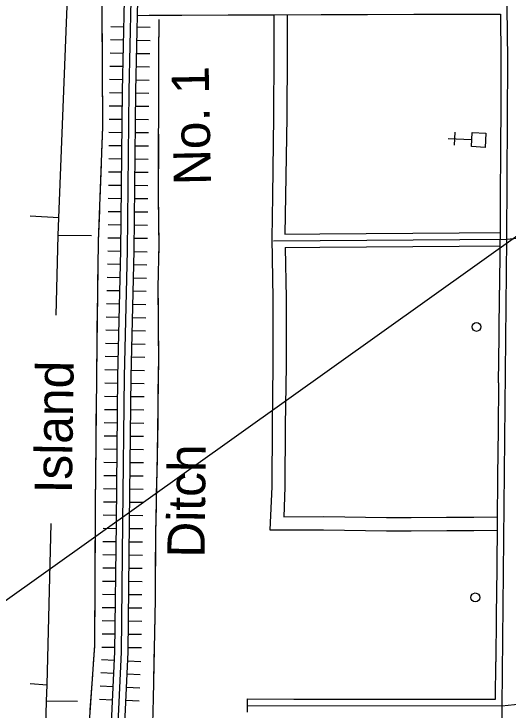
# Model space of a CAD drawing. Extents: x -4306 to 3843, y 131 to 8341.
# Drawn here: x -2826 to -1926, y 1950 to 3215 of the extents above; entities that cross this region are included whole.
import ezdxf

# ---------------------------------------------------------------- set-up
doc = ezdxf.new("R2010")
doc.units = 0
for name, color, linetype in [('31', 7, 'Continuous'), ('32', 7, 'Continuous'), ('4', 7, 'Continuous'), ('45', 7, 'Continuous'), ('46', 7, 'Continuous'), ('50', 7, 'Continuous'), ('52', 7, 'Continuous'), ('56', 7, 'Continuous'), ('57', 7, 'Continuous'), ('58', 7, 'Continuous'), ('63', 7, 'Continuous')]:
    doc.layers.add(name, color=color, linetype=linetype)

msp = doc.modelspace()

# ---------------------------------------------------------------- linework, layer by layer
at = {"layer": '31'}
for p, q in [((-1940.2, 3215.1), (-1939.2, 3135.4)), ((-1939.2, 3133.3), (-1939.6, 3051.1)), ((-1939.2, 3135.4), (-1939.2, 3133.3)), ((-1940.5, 2882.2), (-1940.9, 2817.8)), ((-1940.9, 2817.8), (-1941.1, 2793.8)), ((-1941.1, 2793.8), (-1941.9, 2713.3)), ((-1943.6, 2544.3), (-1944.4, 2459.8)), ((-1944.4, 2459.8), (-1945.3, 2375.3)), ((-1947, 2206.3), (-1947.9, 2121.9)), ((-1947.9, 2121.9), (-1948.7, 2037.4))]:
    msp.add_line(p, q, dxfattribs=at)
for points in [[(-1939.6, 3051.1), (-1940.1, 2966.7)], [(-1940.1, 2966.7), (-1940.5, 2882.2)], [(-1942.7, 2628.8), (-1941.9, 2713.3)], [(-1943.6, 2544.3), (-1942.7, 2628.8)], [(-1945.3, 2375.3), (-1946.2, 2290.8)], [(-1946.2, 2290.8), (-1947, 2206.3)], [(-1949.4, 1969.3), (-1948.7, 2037.4)]]:
    msp.add_lwpolyline(points, dxfattribs=at)
at = {"layer": '32'}
for p, q in [((-2097.6, 3214.6), (-2013.1, 3214.8)), ((-2013.1, 3214.8), (-1940.2, 3215.1)), ((-2601, 3212.3), (-2579.6, 3213)), ((-2579.6, 3213), (-2520.1, 3213.2)), ((-2520.1, 3213.2), (-2435.6, 3213.5)), ((-2435.6, 3213.5), (-2351.1, 3213.7)), ((-2351.1, 3213.7), (-2266.6, 3214)), ((-2266.6, 3214), (-2182.1, 3214.3)), ((-2182.1, 3214.3), (-2097.6, 3214.6)), ((-2353.3, 2802.5), (-1928.9, 2805.9)), ((-1928.9, 2805.9), (-1902.7, 2808.2)), ((-2400.7, 1945.8), (-2400.7, 1969.8)), ((-2400.7, 1969.8), (-2316.2, 1969.7)), ((-2316.2, 1969.7), (-2231.7, 1969.6)), ((-2231.7, 1969.6), (-2147.2, 1969.5)), ((-2147.2, 1969.5), (-2062.7, 1969.4)), ((-2062.7, 1969.4), (-1978.2, 1969.3)), ((-1978.2, 1969.3), (-1949.4, 1969.3))]:
    msp.add_line(p, q, dxfattribs=at)
for points in [[(-1983.5, 5826.9), (-1984.2, 5591.9), (-1978, 5580.6), (-1963.1, 5563), (-1953.4, 5550.1), (-1949.6, 5541.7), (-1948.4, 5534.6), (-1931.5, 5392.4), (-1927.1, 4704.6), (-1924.6, 4492.3), (-1929.1, 4070.4), (-1927.7, 3649.7), (-1928.3, 3227.1), (-1927.2, 3133.3)], [(-1927.2, 3133.3), (-1928.9, 2805.9), (-1937.5, 1957.3), (-1941.9, 1537.3), (-1945.9, 1118.2), (-1949.1, 657.8)], [(-2400.7, 1957.8), (-1937.5, 1957.3), (-1903.3, 1961)]]:
    msp.add_lwpolyline(points, dxfattribs=at)
at = {"layer": '4'}
for p, q in [((-2744, 2844.4), (-2726.5, 3275.8)), ((-2744.8, 2812.3), (-2744, 2844.4)), ((-2748.4, 2667.5), (-2744.8, 2812.3)), ((-2765.3, 1995.4), (-2757.9, 2289.1)), ((-2766, 1965.6), (-2765.3, 1995.4)), ((-2777.4, 1601.5), (-2766, 1965.6))]:
    msp.add_line(p, q, dxfattribs=at)
at = {"layer": '45'}
for p, q in [((-2268.9, 2815.2), (-2184.4, 2815.9)), ((-2184.4, 2815.9), (-2099.9, 2816.5)), ((-2099.9, 2816.5), (-2015.4, 2817.2)), ((-2015.4, 2817.2), (-1940.9, 2817.8)), ((-2268.7, 2791.2), (-2184.2, 2791.9)), ((-2184.2, 2791.9), (-2099.7, 2792.5)), ((-2099.7, 2792.5), (-2015.3, 2793.2)), ((-2015.3, 2793.2), (-1941.1, 2793.8))]:
    msp.add_line(p, q, dxfattribs=at)
at = {"layer": '46'}
for p, q in [((-2627.9, 3075.7), (-2624.3, 3240.8)), ((-2603.9, 3075.4), (-2600.3, 3240.4)), ((-2352.6, 3213.7), (-2352.4, 3143.4)), ((-2328.6, 3213.8), (-2328.4, 3143.4)), ((-2352.4, 3143.4), (-2353.1, 3027.9)), ((-2328.4, 3143.4), (-2329.1, 3027.7)), ((-2630.8, 2785), (-2627.9, 3075.7)), ((-2606.8, 2784.6), (-2603.9, 3075.4)), ((-2353.1, 3027.9), (-2355.2, 2884.8)), ((-2329.1, 3027.7), (-2331.2, 2884.4)), ((-2355.2, 2884.8), (-2356.5, 2807)), ((-2331.2, 2884.4), (-2332.4, 2814.6)), ((-2332.4, 2814.6), (-2268.9, 2815.2)), ((-2356.5, 2807), (-2354.4, 2698.3)), ((-2636.3, 2556.6), (-2630.8, 2785)), ((-2612.3, 2556.2), (-2606.8, 2784.6)), ((-2332.2, 2790.6), (-2268.7, 2791.2)), ((-2332.2, 2790.6), (-2330.4, 2698.5)), ((-2354.4, 2698.3), (-2354.4, 2575.9)), ((-2330.4, 2698.5), (-2330.4, 2575.7)), ((-2354.4, 2575.9), (-2355.8, 2467.4)), ((-2330.4, 2575.7), (-2331.8, 2467.2)), ((-2639.1, 2290.6), (-2636.3, 2556.6)), ((-2615.1, 2290.4), (-2612.3, 2556.2)), ((-2355.8, 2467.4), (-2356.3, 2355.3)), ((-2331.8, 2467.2), (-2332.3, 2354.8)), ((-2356.3, 2355.3), (-2359.6, 2277.2)), ((-2332.3, 2354.8), (-2334.6, 2301.2)), ((-2334.6, 2301.2), (-2261.8, 2301.4)), ((-2261.8, 2301.4), (-2147.3, 2299.7)), ((-2147.3, 2299.7), (-2102.5, 2299.5)), ((-2102.5, 2299.5), (-2038.1, 2300.3)), ((-2038.1, 2300.3), (-1988.5, 2300.4)), ((-1988.5, 2300.4), (-1946.1, 2300.8)), ((-2641.6, 2055.5), (-2639.1, 2290.6)), ((-2617.6, 2054.8), (-2615.1, 2290.4)), ((-2359.6, 2277.2), (-2262, 2277.4)), ((-2262, 2277.4), (-2147.5, 2275.7)), ((-2147.5, 2275.7), (-2102.4, 2275.5)), ((-2102.4, 2275.5), (-2038, 2276.3)), ((-2038, 2276.3), (-1988.4, 2276.4)), ((-1988.4, 2276.4), (-1946.3, 2276.8)), ((-2647.9, 1926.2), (-2641.6, 2055.5)), ((-2623.9, 1924.4), (-2617.6, 2054.8))]:
    msp.add_line(p, q, dxfattribs=at)
at = {"layer": '50'}
msp.add_line((-2855, 2139.1), (-750.7, 3638.5), dxfattribs=at)
at = {"layer": '52'}
for p, q in [((-2744, 2844.4), (-2796.1, 2847.8)), ((-2684.1, 2812), (-2744.8, 2812.3)), ((-2796.1, 1997.9), (-2765.3, 1995.4)), ((-2709.8, 1965.1), (-2766, 1965.6))]:
    msp.add_line(p, q, dxfattribs=at)
at = {"layer": '56'}
for points in [[(-2660, 3586), (-2656.1, 3526.9), (-2651.5, 3482.5), (-2665.7, 3236.5), (-2664.4, 3010), (-2672.3, 2802.1), (-2674.8, 2612), (-2677.7, 2321.3), (-2678.8, 2067.8), (-2689.4, 1918.9), (-2710.5, 1764.8), (-2721.4, 1657.8), (-2742.6, 1525.3)], [(-2562, 3205), (-2562.3, 3143.3), (-2562.3, 3134.2)], [(-2562, 3205), (-2562.1, 3173.3)], [(-2665.5, 3196), (-2665.1, 3132.6)], [(-2562.2, 3152.2), (-2562.3, 3143.3), (-2562.3, 3134.2)], [(-2562.3, 3134.2), (-2562.8, 2880.1), (-2562.1, 2796.8), (-2563.5, 2718.1), (-2562.6, 2589.4), (-2564.7, 2414.6), (-2568.1, 2271.2), (-2568.8, 2150.6), (-2572.3, 1970.7), (-2573.4, 1924.5), (-2574.5, 1844.9), (-2574, 1763.3), (-2574.4, 1689.7), (-2575.9, 1554)], [(-2562.3, 3134.2), (-2562.4, 3102.5)], [(-2665, 3111.5), (-2664.8, 3079.8)], [(-2664.8, 3079.8), (-2664.6, 3048.1)], [(-2562.4, 3081.4), (-2562.5, 3018.1)], [(-2664.5, 3027), (-2664.4, 3010), (-2666.1, 2963.7)], [(-2562.6, 2996.9), (-2562.7, 2933.6)], [(-2666.9, 2942.6), (-2669.3, 2879.2)], [(-2562.8, 2912.4), (-2562.8, 2880.1), (-2562.6, 2849.1)], [(-2670.1, 2858.1), (-2672.3, 2802.1), (-2672.4, 2794.8)], [(-2562.4, 2828), (-2562.1, 2796.8), (-2562.7, 2764.6)], [(-2672.6, 2773.7), (-2673.5, 2710.3)], [(-2563.1, 2743.5), (-2563.5, 2718.1), (-2563.2, 2680.1)], [(-2673.8, 2689.2), (-2674.6, 2625.8)], [(-2563.1, 2659), (-2562.9, 2627.3)], [(-2562.9, 2627.3), (-2562.6, 2595.6)], [(-2674.9, 2604.7), (-2675.2, 2573)], [(-2675.2, 2573), (-2675.5, 2541.4)], [(-2562.8, 2574.5), (-2563.5, 2511.1)], [(-2675.7, 2520.2), (-2676.3, 2456.9)], [(-2563.8, 2490), (-2564.5, 2426.7)], [(-2676.5, 2435.8), (-2677.2, 2372.4)], [(-2564.9, 2405.5), (-2566.4, 2342.2)], [(-2677.4, 2351.3), (-2677.7, 2321.3), (-2677.8, 2287.9)], [(-2566.9, 2321.1), (-2568.1, 2271.2), (-2568.2, 2257.7)], [(-2677.9, 2266.8), (-2678.2, 2203.4)], [(-2568.3, 2236.6), (-2568.6, 2173.2)], [(-2678.3, 2182.3), (-2678.5, 2118.9)], [(-2568.7, 2152.1), (-2568.8, 2150.6), (-2569.4, 2120.4)], [(-2569.4, 2120.4), (-2570, 2088.8)], [(-2678.6, 2097.8), (-2678.8, 2067.8), (-2678.9, 2066.1)], [(-2678.9, 2066.1), (-2681.1, 2034.5)], [(-2570.4, 2067.6), (-2571.7, 2004.3)], [(-2682.6, 2013.5), (-2687.2, 1950.3)], [(-2572.1, 1983.2), (-2572.3, 1970.7), (-2573.4, 1924.5), (-2573.4, 1919.8)]]:
    msp.add_lwpolyline(points, dxfattribs=at)
at = {"layer": '57'}
for centre in [(-1983.7, 2646.2), (-1985.9, 2154.5)]:
    msp.add_circle(centre, 8, dxfattribs=at)
at = {"layer": '58'}
for p, q in [((-2023.7, 2976.5), (-2022.5, 3000.4)), ((-2035.1, 2989), (-1992.1, 2986.9))]:
    msp.add_line(p, q, dxfattribs=at)
msp.add_lwpolyline([(-1967.8, 2972.7), (-1992.7, 2974), (-1991.5, 2999.8), (-1966.5, 2998.6)], close=True, dxfattribs=at)
at = {"layer": '63'}
for p, q in [((-2615.9, 3075.5), (-2612.3, 3240.6)), ((-2625.4, 3191.5), (-2649.4, 3192)), ((-2577.4, 3190.5), (-2601.4, 3191)), ((-2625.9, 3167.5), (-2649.9, 3168)), ((-2625.9, 3167.5), (-2649.9, 3168)), ((-2577.9, 3166.5), (-2601.9, 3167)), ((-2577.9, 3166.5), (-2601.9, 3167)), ((-2626.4, 3143.5), (-2650.4, 3144)), ((-2578.4, 3142.5), (-2602.4, 3143)), ((-2627, 3119.5), (-2651, 3120)), ((-2579, 3118.5), (-2603, 3119)), ((-2627.5, 3095.5), (-2651.5, 3096)), ((-2627.5, 3095.5), (-2651.5, 3096)), ((-2579.5, 3094.5), (-2603.5, 3095)), ((-2579.5, 3094.5), (-2603.5, 3095)), ((-2618.8, 2784.8), (-2615.9, 3075.5)), ((-2627.9, 3071.4), (-2651.9, 3071.6)), ((-2579.9, 3070.9), (-2603.9, 3071.1)), ((-2628.2, 3047.4), (-2652.2, 3047.6)), ((-2580.2, 3046.9), (-2604.2, 3047.1)), ((-2628.4, 3023.4), (-2652.4, 3023.6)), ((-2628.4, 3023.4), (-2652.4, 3023.6)), ((-2580.4, 3022.9), (-2604.4, 3023.1)), ((-2580.4, 3022.9), (-2604.4, 3023.1)), ((-2628.7, 2999.4), (-2652.7, 2999.6)), ((-2580.7, 2998.9), (-2604.7, 2999.1)), ((-2628.9, 2975.4), (-2652.9, 2975.6)), ((-2580.9, 2974.9), (-2604.9, 2975.1)), ((-2629.1, 2951.4), (-2653.1, 2951.6)), ((-2629.1, 2951.4), (-2653.1, 2951.6)), ((-2581.1, 2950.9), (-2605.1, 2951.1)), ((-2581.1, 2950.9), (-2605.1, 2951.1)), ((-2629.4, 2927.4), (-2653.4, 2927.6)), ((-2581.4, 2926.9), (-2605.4, 2927.1)), ((-2629.6, 2903.4), (-2653.6, 2903.6)), ((-2581.6, 2902.9), (-2605.6, 2903.1)), ((-2629.9, 2879.4), (-2653.9, 2879.6)), ((-2629.9, 2879.4), (-2653.9, 2879.6)), ((-2581.8, 2878.9), (-2605.9, 2879.1)), ((-2581.8, 2878.9), (-2605.9, 2879.1)), ((-2630.1, 2855.4), (-2654.1, 2855.6)), ((-2582.1, 2854.9), (-2606.1, 2855.1)), ((-2630.3, 2831.4), (-2654.3, 2831.6)), ((-2582.3, 2830.9), (-2606.3, 2831.1)), ((-2630.6, 2807.4), (-2654.6, 2807.6)), ((-2630.6, 2807.4), (-2654.6, 2807.6)), ((-2582.6, 2806.9), (-2606.6, 2807.1)), ((-2582.6, 2806.9), (-2606.6, 2807.1)), ((-2624.3, 2556.4), (-2618.8, 2784.8)), ((-2630.8, 2783.5), (-2654.8, 2784.1)), ((-2582.8, 2782.4), (-2606.8, 2783)), ((-2631.4, 2759.5), (-2655.4, 2760.1)), ((-2583.4, 2758.4), (-2607.4, 2759)), ((-2632, 2735.5), (-2656, 2736.1)), ((-2632, 2735.5), (-2656, 2736.1)), ((-2584, 2734.4), (-2608, 2735)), ((-2584, 2734.4), (-2608, 2735)), ((-2632.6, 2711.6), (-2656.6, 2712.1)), ((-2584.6, 2710.4), (-2608.6, 2711)), ((-2633.1, 2687.6), (-2657.1, 2688.1)), ((-2585.2, 2686.4), (-2609.1, 2687)), ((-2633.7, 2663.6), (-2657.7, 2664.1)), ((-2633.7, 2663.6), (-2657.7, 2664.1)), ((-2585.7, 2662.4), (-2609.7, 2663)), ((-2585.7, 2662.4), (-2609.7, 2663)), ((-2634.3, 2639.6), (-2658.3, 2640.1)), ((-2586.3, 2638.4), (-2610.3, 2639)), ((-2634.9, 2615.6), (-2658.9, 2616.1)), ((-2586.9, 2614.4), (-2610.9, 2615)), ((-2635.5, 2591.6), (-2659.5, 2592.2)), ((-2635.5, 2591.6), (-2659.5, 2592.2)), ((-2587.5, 2590.4), (-2611.5, 2591)), ((-2587.5, 2590.4), (-2611.5, 2591)), ((-2636, 2567.6), (-2660, 2568.2)), ((-2588, 2566.4), (-2612, 2567)), ((-2627.1, 2290.5), (-2624.3, 2556.4)), ((-2636.4, 2543.4), (-2660.4, 2543.7)), ((-2588.4, 2542.9), (-2612.4, 2543.2)), ((-2636.7, 2519.4), (-2660.7, 2519.7)), ((-2636.7, 2519.4), (-2660.7, 2519.7)), ((-2588.7, 2518.9), (-2612.7, 2519.2)), ((-2588.7, 2518.9), (-2612.7, 2519.2)), ((-2636.9, 2495.4), (-2661, 2495.7)), ((-2588.9, 2494.9), (-2612.9, 2495.2)), ((-2637.2, 2471.4), (-2661.2, 2471.7)), ((-2589.2, 2470.9), (-2613.2, 2471.2)), ((-2637.5, 2447.4), (-2661.5, 2447.7)), ((-2637.5, 2447.4), (-2661.5, 2447.7)), ((-2589.5, 2446.9), (-2613.5, 2447.2)), ((-2589.5, 2446.9), (-2613.5, 2447.2)), ((-2637.7, 2423.4), (-2661.7, 2423.7)), ((-2589.7, 2422.9), (-2613.7, 2423.2)), ((-2638, 2399.4), (-2662, 2399.7)), ((-2590, 2398.9), (-2614, 2399.2)), ((-2638.2, 2375.4), (-2662.2, 2375.7)), ((-2638.2, 2375.4), (-2662.2, 2375.7)), ((-2590.2, 2374.9), (-2614.2, 2375.2)), ((-2590.2, 2374.9), (-2614.2, 2375.2)), ((-2638.5, 2351.4), (-2662.5, 2351.7)), ((-2590.5, 2350.9), (-2614.5, 2351.2)), ((-2638.7, 2327.4), (-2662.7, 2327.7)), ((-2590.7, 2326.9), (-2614.7, 2327.2)), ((-2639, 2303.4), (-2663, 2303.7)), ((-2639, 2303.4), (-2663, 2303.7)), ((-2591, 2302.9), (-2615, 2303.2)), ((-2591, 2302.9), (-2615, 2303.2)), ((-2639.2, 2279.4), (-2663.2, 2279.7)), ((-2629.6, 2055.2), (-2627.1, 2290.5)), ((-2591.2, 2278.9), (-2615.2, 2279.2)), ((-2639.5, 2255.4), (-2663.5, 2255.7)), ((-2591.5, 2254.9), (-2615.5, 2255.1)), ((-2639.7, 2231.4), (-2663.7, 2231.6)), ((-2639.7, 2231.4), (-2663.7, 2231.6)), ((-2591.7, 2230.9), (-2615.7, 2231.1)), ((-2591.7, 2230.9), (-2615.7, 2231.1)), ((-2640, 2207.4), (-2664, 2207.6)), ((-2592, 2206.9), (-2616, 2207.1)), ((-2640.2, 2183.4), (-2664.2, 2183.6)), ((-2592.2, 2182.9), (-2616.2, 2183.1)), ((-2640.5, 2159.4), (-2664.5, 2159.6)), ((-2640.5, 2159.4), (-2664.5, 2159.6)), ((-2592.5, 2158.9), (-2616.5, 2159.1)), ((-2592.5, 2158.9), (-2616.5, 2159.1)), ((-2640.7, 2135.4), (-2664.7, 2135.6)), ((-2592.7, 2134.9), (-2616.7, 2135.1)), ((-2641, 2111.4), (-2665, 2111.6)), ((-2593, 2110.9), (-2617, 2111.1)), ((-2641.2, 2087.4), (-2665.2, 2087.6)), ((-2641.2, 2087.4), (-2665.2, 2087.6)), ((-2593.2, 2086.9), (-2617.2, 2087.1)), ((-2593.2, 2086.9), (-2617.2, 2087.1)), ((-2641.5, 2063.4), (-2665.5, 2063.6)), ((-2593.5, 2062.9), (-2617.5, 2063.1)), ((-2635.9, 1925.3), (-2629.6, 2055.2)), ((-2642.3, 2039.9), (-2666.3, 2041)), ((-2594.4, 2037.5), (-2618.4, 2038.7)), ((-2643.5, 2015.9), (-2667.5, 2017.1)), ((-2643.5, 2015.9), (-2667.5, 2017.1)), ((-2595.6, 2013.5), (-2619.5, 2014.7)), ((-2595.6, 2013.5), (-2619.5, 2014.7)), ((-2644.7, 1991.9), (-2668.7, 1993.1)), ((-2596.7, 1989.6), (-2620.7, 1990.7)), ((-2645.9, 1967.9), (-2669.8, 1969.1)), ((-2597.9, 1965.6), (-2621.9, 1966.8))]:
    msp.add_line(p, q, dxfattribs=at)

# ---------------------------------------------------------------- texts
at = {"layer": '56'}
for s, rotation, p in [('No. 1', 91.1621, (-2466.8, 2904.6)), ('Island', 89.1621, (-2720.2, 2343.1)), ('Ditch', 89.333, (-2478.8, 2226.4))]:
    msp.add_text(s, height=67.59, rotation=rotation, dxfattribs=at).set_placement(p)

doc.saveas('drawing.dxf')
